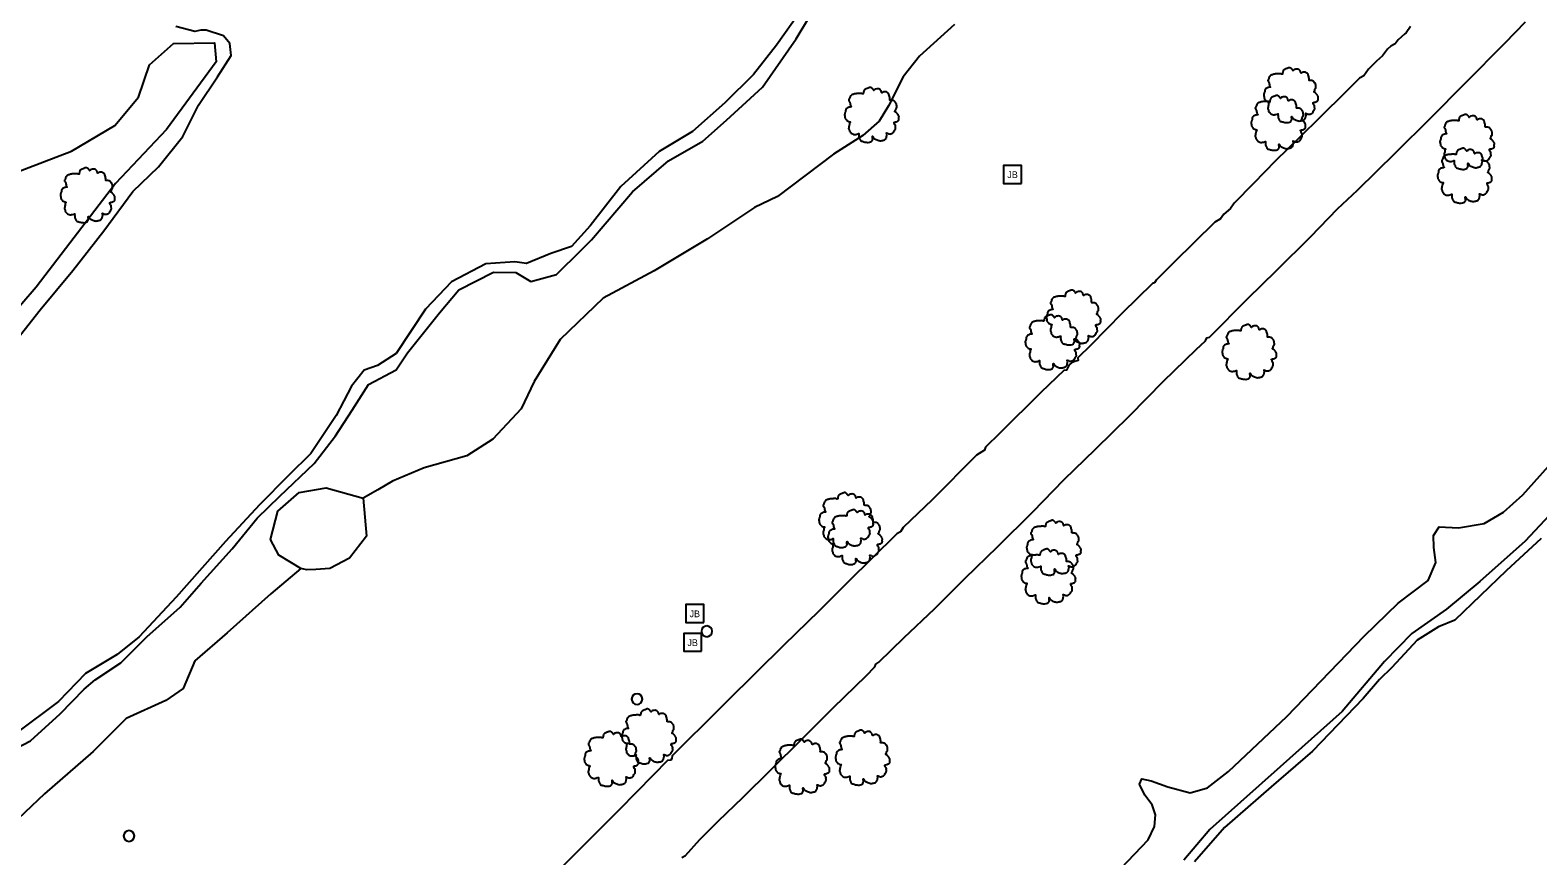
# Model space of a CAD drawing. Extents: x 2160437 to 2172832, y 205694 to 212444.
# Drawn here: x 2172011.7 to 2172432.5, y 206594.6 to 206825.1 of the extents above; entities that cross this region are included whole.
import ezdxf

# ---------------------------------------------------------------- set-up
doc = ezdxf.new("R2010")
doc.units = 0
for name, color, linetype in [('Default', 7, 'Continuous'), ('RD_EX_DR_Inlet', 7, 'Continuous'), ('RD_EX_H2O', 7, 'Continuous'), ('RD_EX_Road', 7, 'Continuous'), ('RD_EX_Road_Post', 7, 'Continuous'), ('RD_EX_VEG', 7, 'Continuous'), ('RD_EX_VEG_ShrubLine', 7, 'Continuous'), ('RD_EX_VEG_TreeLine', 7, 'Continuous')]:
    doc.layers.add(name, color=color, linetype=linetype)

# ---------------------------------------------------------------- blocks, each defined once
blk = doc.blocks.new('POST')
at = {"layer": 'Default'}
for start, end in [(90, 270), (270, 90)]:
    blk.add_arc((0, 0), 0.0417, start, end, dxfattribs=at)
blk = doc.blocks.new('T2')
at = {"layer": 'RD_EX_VEG'}
for points in [[(0.05, 7.21), (-0.25, 7.24), (-0.57, 7.14), (-0.82, 7.04), (-1.05, 6.96), (-1.27, 6.86), (-1.57, 6.69), (-1.8, 6.49), (-1.92, 6.24), (-1.97, 6.01), (-2.02, 5.74), (-2.02, 5.56), (-2.15, 5.54), (-2.3, 5.56), (-2.55, 5.64), (-2.8, 5.64), (-3.05, 5.64), (-3.4, 5.61), (-3.75, 5.61), (-4.02, 5.56), (-4.35, 5.51), (-4.72, 5.39), (-5.07, 5.26), (-5.37, 5.01), (-5.62, 4.54), (-5.75, 4.19), (-5.9, 3.94), (-5.75, 3.49), (-5.57, 3.14), (-5.55, 2.94), (-5.47, 2.52), (-5.37, 2.29), (-5.25, 2.09), (-5.32, 2.07), (-5.7, 2.02), (-6, 1.92), (-6.42, 1.69), (-6.64, 1.47), (-6.74, 1.14), (-6.77, 0.79), (-6.87, 0.59), (-6.94, 0.32), (-6.97, 0.24), (-7.02, -0.08), (-6.92, -0.53), (-6.89, -0.88), (-6.77, -1.11), (-6.62, -1.28), (-6.44, -1.53), (-6.05, -1.76), (-5.72, -1.86), (-5.52, -1.88), (-5.7, -2.38), (-5.75, -2.73), (-5.87, -3.13), (-5.87, -3.21), (-5.92, -3.68), (-5.77, -4.01), (-5.7, -4.38), (-5.52, -4.61), (-5.25, -4.91), (-4.92, -5.13), (-4.42, -5.26), (-4.02, -5.23), (-3.45, -5.06), (-3.2, -4.98), (-3.22, -5.16), (-3.2, -5.53), (-3.2, -5.96), (-3.05, -6.28), (-2.95, -6.56), (-2.8, -6.81), (-2.47, -7.03), (-2.07, -7.11), (-1.65, -7.26), (-1.2, -7.33), (-0.7, -7.36), (-0.1, -7.21), (0.18, -7.08), (0.28, -6.91), (0.48, -6.53), (0.43, -6.31), (0.45, -5.71), (0.55, -5.88), (0.73, -6.23), (1.23, -6.53), (1.63, -6.71), (2.1, -6.86), (2.4, -6.93), (2.88, -6.86), (3.25, -6.78), (3.63, -6.66), (3.93, -6.38), (4.1, -6.11), (4.15, -5.83), (4.23, -5.46), (4.28, -5.28)], [(4.28, -5.28), (4.2, -5.11), (4.15, -4.86), (4.23, -4.88), (4.4, -4.93), (4.68, -5.06), (4.9, -5.13), (5.23, -5.11), (5.5, -5.01), (5.95, -4.73), (6.22, -4.26), (6.5, -3.86), (6.57, -3.53), (6.52, -3.31), (6.5, -2.81), (6.3, -2.56), (6.25, -2.43), (6.15, -2.03), (6.22, -1.98), (6.5, -1.93), (6.87, -1.81), (7.15, -1.68), (7.37, -1.51), (7.45, -1.28), (7.42, -0.88), (7.47, -0.48), (7.4, -0.33), (7.3, -0.18), (7.22, 0.02), (7.07, 0.17), (6.97, 0.32), (6.87, 0.42), (6.75, 0.57), (6.57, 0.69), (6.42, 0.74), (6.37, 0.89), (6.52, 1.09), (6.57, 1.19), (6.6, 1.42), (6.82, 1.77), (6.87, 2.17), (6.82, 2.59), (6.77, 2.87), (6.62, 3.14), (6.42, 3.39), (6.3, 3.56), (6.12, 3.69), (5.8, 3.81), (5.55, 3.86), (5.2, 3.86), (5, 3.91), (5.03, 3.96), (5.03, 4.11), (5.03, 4.39), (4.95, 4.84), (4.8, 5.34), (4.8, 5.36), (4.7, 5.61), (4.48, 5.81), (4.3, 5.91), (4.1, 6.04), (3.85, 6.06), (3.55, 6.06), (3.28, 6.01), (3.08, 5.91), (2.9, 5.79), (2.83, 5.94), (2.73, 6.24), (2.68, 6.39), (2.53, 6.56), (2.3, 6.76), (1.85, 6.89), (1.23, 6.81), (0.93, 6.61), (0.78, 6.44), (0.73, 6.56), (0.53, 6.76), (0.43, 6.94), (0.25, 7.06), (0.1, 7.16), (0, 7.21)]]:
    blk.add_spline(points, degree=3, dxfattribs=at)

msp = doc.modelspace()

# ---------------------------------------------------------------- linework, layer by layer
at = {"layer": 'RD_EX_DR_Inlet'}
for p, q in [((2172288.41, 206782.36), (2172288.41, 206787.36)), ((2172199.72, 206659.73), (2172199.72, 206664.73)), ((2172199.13, 206651.68), (2172199.13, 206656.68))]:
    msp.add_line(p, q, dxfattribs=at)
for points in [[(2172288.41, 206782.36), (2172288.41, 206787.36), (2172283.41, 206787.36), (2172283.41, 206782.36)], [(2172199.72, 206659.73), (2172199.72, 206664.73), (2172194.72, 206664.73), (2172194.72, 206659.73)], [(2172199.13, 206651.68), (2172199.13, 206656.68), (2172194.13, 206656.68), (2172194.13, 206651.68)]]:
    msp.add_lwpolyline(points, close=True, dxfattribs=at)
at = {"layer": 'RD_EX_H2O'}
for points in [[(2172226.61, 206830.23), (2172220.05, 206820.92), (2172213.57, 206812.73), (2172205.61, 206804.8), (2172196.58, 206796.82), (2172187.28, 206791.3), (2172176.55, 206781.45), (2172168.06, 206770.47), (2172162.83, 206764.75), (2172157.04, 206762.74), (2172150.21, 206759.94), (2172146.98, 206760.41), (2172138.9, 206759.86), (2172129.3, 206754.88), (2172122.03, 206747.26), (2172113.85, 206734.88), (2172108.63, 206731.49), (2172104.91, 206730.15), (2172101.4, 206725.72), (2172097.12, 206717.53), (2172090.06, 206706.93), (2172083.86, 206700.74), (2172075.72, 206692.55), (2172066.25, 206682.33), (2172052.47, 206666.84), (2172042.17, 206655.73), (2172036.02, 206650.84), (2172027.21, 206645.5), (2172019.66, 206637.7), (2172007.79, 206628.79)], [(2172007, 206737.47), (2172014.51, 206747.07), (2172023.63, 206758.06), (2172032.26, 206769.07), (2172040.36, 206780.07), (2172047.51, 206786.99), (2172054.29, 206795.45), (2172058.72, 206804.18), (2172064.05, 206812.13), (2172067.86, 206818.1), (2172067.49, 206821.37), (2172065.69, 206823.52), (2172060.83, 206825.1), (2172059.36, 206825.11), (2172057.7, 206824.78), (2172052.41, 206826.2)], [(2172433.48, 206683.19), (2172423.66, 206674.19), (2172409.31, 206660.36), (2172404.76, 206658.51), (2172398.85, 206654.84), (2172391.75, 206647.15), (2172388.33, 206643.83), (2172383.78, 206638.48), (2172369.59, 206623.84), (2172358.04, 206613.83), (2172345.03, 206602.47), (2172336.66, 206592.92)]]:
    msp.add_lwpolyline(points, dxfattribs=at)
at = {"layer": 'RD_EX_Road'}
for points in [[(2172397.01, 206826.15), (2172395.79, 206824.41), (2172395.37, 206824.09), (2172393.51, 206822.46), (2172393.51, 206822.46), (2172392.66, 206821.36), (2172391.52, 206820.69), (2172390.51, 206819.86), (2172389.19, 206818.01), (2172387.5, 206816.47), (2172385.21, 206814.21), (2172383.93, 206812.39), (2172382.7, 206811.76), (2172378.67, 206807.62), (2172371.96, 206801.02), (2172365.92, 206795.04), (2172359.34, 206788.68), (2172353.14, 206782.28), (2172347.72, 206776.81), (2172346.71, 206775.3), (2172344.83, 206773.72), (2172343.93, 206772.41), (2172342.4, 206771.49), (2172330.95, 206760.27), (2172326.03, 206755.3), (2172325.54, 206754.54), (2172324.93, 206754.38), (2172316.48, 206746.07), (2172307.72, 206737.21), (2172304.14, 206733.63), (2172304.2, 206732.87), (2172303.04, 206732.49), (2172302.37, 206732.24), (2172301.69, 206731.64), (2172300.94, 206730.21), (2172300.18, 206730.08), (2172293.92, 206724.05), (2172282.32, 206712.62), (2172278.35, 206708.66), (2172278.06, 206707.86), (2172275.82, 206706.42), (2172263.45, 206694.02), (2172255.34, 206686.24), (2172254.62, 206685.05), (2172253.57, 206684.46), (2172239.94, 206671), (2172231.84, 206662.93), (2172222.13, 206653.52), (2172206.14, 206637.66), (2172204.18, 206635.74), (2172190.94, 206622.53), (2172190.83, 206621.72), (2172190.57, 206621.31), (2172189.58, 206621.2), (2172185.63, 206617.13), (2172176.07, 206607.45), (2172165.23, 206596.56), (2172153.97, 206585.2)], [(2172193.62, 206594.14), (2172194.66, 206594.7), (2172198.66, 206599.1), (2172203.82, 206604.34), (2172210.65, 206610.89), (2172218.42, 206618.6), (2172227.2, 206627.28), (2172235.92, 206636), (2172245.02, 206644.83), (2172247.51, 206647.31), (2172247.75, 206648.06), (2172248.56, 206648.63), (2172255.66, 206655.56), (2172264.09, 206663.58), (2172272.67, 206672.12), (2172281.66, 206680.87), (2172291.53, 206690.63), (2172300.33, 206699.63), (2172309.08, 206708.09), (2172318.66, 206717.53), (2172328.08, 206727.14), (2172337.13, 206735.97), (2172339.78, 206738.41), (2172340.11, 206739.19), (2172340.84, 206739.42), (2172351.61, 206750.19), (2172359.46, 206757.95), (2172369.11, 206767.54), (2172376.57, 206775.27), (2172382.15, 206780.49), (2172392.87, 206791), (2172402.42, 206800.44), (2172412.33, 206810.44), (2172423.36, 206821.58), (2172429.11, 206827.43)]]:
    msp.add_lwpolyline(points, dxfattribs=at)
at = {"layer": 'RD_EX_VEG_ShrubLine'}
for points in [[(2172002.5, 206621.82), (2172011.8, 206626.69), (2172020.09, 206634.26), (2172026.78, 206641.13), (2172029.91, 206643.75), (2172036.99, 206648.45), (2172044.3, 206655.73), (2172053.63, 206664.05), (2172059.41, 206670.69), (2172068.08, 206680.34), (2172075.08, 206688.83), (2172081.4, 206695.01), (2172090.99, 206704.12), (2172096.95, 206711.85), (2172101.55, 206719.04), (2172106.18, 206726.21), (2172113.83, 206730.28), (2172117.06, 206734.99), (2172125.98, 206746.24), (2172131.4, 206752.67), (2172141.04, 206757.59), (2172147.3, 206757.49), (2172151.44, 206754.99), (2172158.6, 206756.94), (2172165.5, 206763.73), (2172168.43, 206766.6), (2172179.81, 206779.98), (2172189.9, 206788.64), (2172199.5, 206794.13), (2172206.11, 206800.03), (2172216.13, 206809.25), (2172225.53, 206822.68), (2172232.32, 206834.12)], [(2172269.66, 206826.75), (2172259.89, 206817.84), (2172255.35, 206812.06), (2172251.28, 206804.05), (2172248.68, 206799.72), (2172244.12, 206795.75), (2172235.89, 206790.49), (2172220.26, 206778.73), (2172213.86, 206775.6), (2172200.79, 206766.91), (2172185.88, 206757.9), (2172171.61, 206750.29), (2172159.64, 206738.8), (2172152.35, 206727.03), (2172148.73, 206719.39), (2172140.83, 206710.94), (2172133.64, 206706.23), (2172121.69, 206702.91), (2172112.88, 206699.21), (2172108.78, 206696.82), (2172104.63, 206694.45)], [(2172002.55, 206783.46), (2172023.28, 206791.35), (2172035.35, 206798.52), (2172042, 206806.47), (2172045.06, 206815.43), (2172051.77, 206821.43), (2172063.2, 206821.63), (2172063.63, 206816.3), (2172049.82, 206797.44), (2172035.58, 206782.29), (2172013.38, 206753.33), (2171993.28, 206730.08)], [(2172316.18, 206591.12), (2172323.79, 206599), (2172325.51, 206602.78), (2172325.82, 206606.03), (2172324.86, 206608.8), (2172322.81, 206611.53), (2172321.32, 206614.55), (2172322, 206616.04), (2172324.61, 206615.49), (2172329.25, 206613.8), (2172335.49, 206612.13), (2172340.36, 206613.52), (2172346.15, 206618.09), (2172362.47, 206633.46), (2172384.01, 206655.89), (2172393.51, 206665.13), (2172401.92, 206671.49), (2172404.07, 206676.45), (2172403.44, 206680.65), (2172403.36, 206683.98), (2172404.99, 206686.41), (2172410.4, 206686.18), (2172417.52, 206687.39), (2172422.89, 206690.57), (2172428.37, 206695.39), (2172438.61, 206706.95)], [(2172437.1, 206691.13), (2172429, 206682.41), (2172416.37, 206671.19), (2172407.02, 206663.46), (2172397.34, 206656.63), (2172389.68, 206648.88), (2172377.89, 206634.84), (2172377.89, 206634.84), (2172360.58, 206619.39), (2172349.54, 206609.57), (2172340.97, 206601.92), (2172333.69, 206593.36)], [(2172087.28, 206674.85), (2172078.86, 206667.71), (2172066.68, 206656.8), (2172057.71, 206649.06), (2172054.42, 206641.32), (2172049.6, 206637.93), (2172038.55, 206632.96), (2172029.27, 206623.71), (2172015.76, 206611.91), (2172004.71, 206601.49)]]:
    msp.add_lwpolyline(points, dxfattribs=at)
at = {"layer": 'RD_EX_VEG_TreeLine'}
msp.add_lwpolyline([(2172087.28, 206674.85), (2172081.16, 206678.52), (2172078.8, 206682.92), (2172080.85, 206690.85), (2172086.76, 206696.04), (2172094.33, 206697.38), (2172104.63, 206694.45), (2172105.63, 206683.84), (2172100.87, 206677.68), (2172095.36, 206674.77), (2172091.41, 206674.55), (2172088.9, 206674.43)], close=True, dxfattribs=at)

# ---------------------------------------------------------------- block references
at = {"layer": 'RD_EX_Road_Post', "xscale": 36, "yscale": 36}
for p in [(2172200.56, 206657.27), (2172181.09, 206638.35), (2172039.31, 206600.12)]:
    msp.add_blockref('POST', p, dxfattribs=at)
at = {"layer": 'RD_EX_VEG', "xscale": 1.0499999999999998, "yscale": 1.0499999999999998}
for p in [(2172363.37, 206807.04), (2172246.38, 206801.53), (2172359.86, 206799.31), (2172412.56, 206794), (2172411.87, 206784.56), (2172027.52, 206779.11), (2172302.7, 206744.96), (2172296.82, 206738.09), (2172351.76, 206735.36), (2172239.23, 206688.39), (2172241.74, 206683.64), (2172297.2, 206680.67), (2172295.68, 206672.67), (2172184.19, 206627.98), (2172173.71, 206621.72), (2172243.83, 206622.06), (2172226.99, 206619.54)]:
    msp.add_blockref('T2', p, dxfattribs=at)

# ---------------------------------------------------------------- texts
at = {"layer": 'RD_EX_DR_Inlet'}
for p in [(2172284.44, 206783.84), (2172195.75, 206661.21), (2172195.16, 206653.16)]:
    msp.add_text('JB', height=1.875, dxfattribs=at).set_placement(p)

doc.saveas('drawing.dxf')
